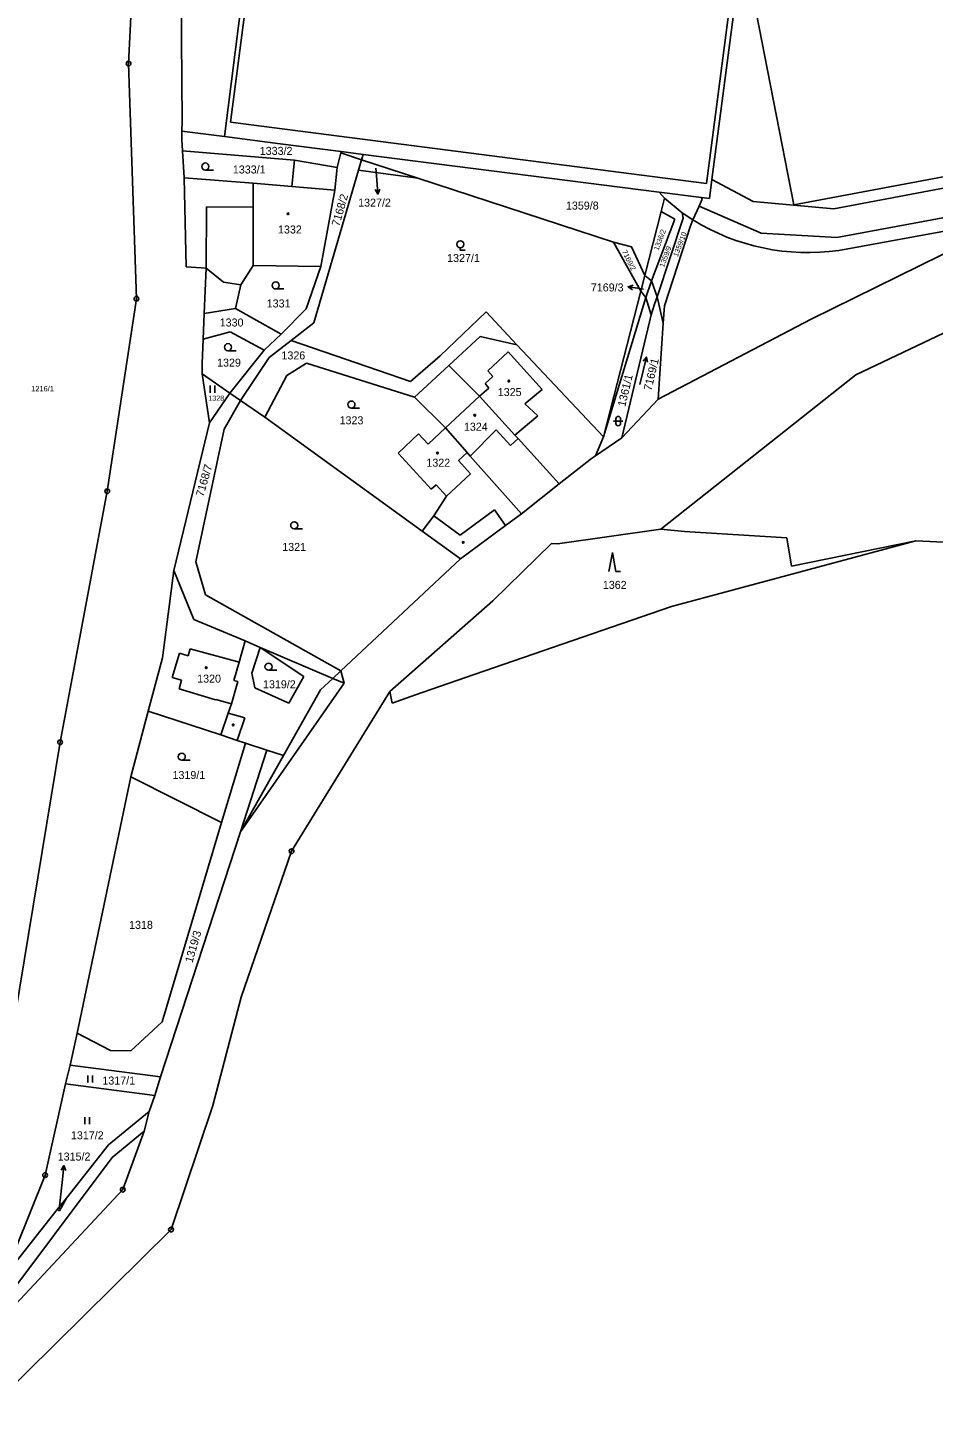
# Model space of a CAD drawing. Extents: x -593183 to -588034, y -1130415 to -1124994.
# Drawn here: x -590703 to -590510.6, y -1129694.1 to -1129397 of the extents above; entities that cross this region are included whole.
import ezdxf

# ---------------------------------------------------------------- set-up
doc = ezdxf.new("R2010")
doc.units = 0
for name, color, linetype in [('Vrstva 1', 7, 'Continuous'), ('Vrstva 13', 7, 'Continuous'), ('Vrstva 16', 7, 'Continuous'), ('Vrstva 18', 7, 'Continuous'), ('Vrstva 19', 7, 'Continuous'), ('Vrstva 24', 7, 'Continuous'), ('Vrstva 25', 7, 'Continuous'), ('Vrstva 4', 7, 'Continuous')]:
    doc.layers.add(name, color=color, linetype=linetype)

msp = doc.modelspace()

# ---------------------------------------------------------------- linework, layer by layer
at = {"layer": 'Vrstva 1'}
for p, q in [((-590652.25, -1129348.91), (-590661.21, -1129420.07)), ((-590651.35, -1129350.59), (-590659.9, -1129417.02)), ((-590558.75, -1129430.04), (-590550.17, -1129363.62)), ((-590681.59, -1129404.55), (-590680.19, -1129377.02)), ((-590557.61, -1129429.2), (-590551.06, -1129379.02)), ((-590670.2, -1129416.87), (-590670.5, -1129384.22)), ((-590679.92, -1129454.5), (-590681.59, -1129404.55)), ((-590670.25, -1129418.92), (-590670.3, -1129420.77)), ((-590670.2, -1129416.87), (-590670.25, -1129418.92)), ((-590661.21, -1129420.07), (-590670.25, -1129418.92)), ((-590659.9, -1129417.02), (-590558.75, -1129430.04)), ((-590670.3, -1129420.77), (-590670.15, -1129423.07)), ((-590661.21, -1129420.07), (-590649.4, -1129421.58)), ((-590649.4, -1129421.58), (-590636.39, -1129423.24)), ((-590670.15, -1129423.07), (-590646.32, -1129425.06)), ((-590669.77, -1129428.8), (-590670.15, -1129423.07)), ((-590646.32, -1129425.06), (-590646.91, -1129430.66)), ((-590637.29, -1129426.62), (-590646.32, -1129425.06)), ((-590636.47, -1129423.54), (-590637.29, -1129426.62)), ((-590636.47, -1129423.54), (-590636.39, -1129423.24)), ((-590632.06, -1129424.98), (-590636.47, -1129423.54)), ((-590636.39, -1129423.24), (-590631.72, -1129423.83)), ((-590632.72, -1129427.22), (-590632.06, -1129424.98)), ((-590632.06, -1129424.98), (-590620.12, -1129428.89)), ((-590631.72, -1129423.83), (-590568.82, -1129431.86)), ((-590632.72, -1129427.22), (-590642.23, -1129459.61)), ((-590637.29, -1129426.62), (-590637.73, -1129431.41)), ((-590632.72, -1129427.22), (-590620.12, -1129428.89)), ((-590655.13, -1129429.99), (-590669.77, -1129428.8)), ((-590669.77, -1129428.8), (-590669.38, -1129447.73)), ((-590646.91, -1129430.66), (-590655.13, -1129429.99)), ((-590578.55, -1129442.49), (-590620.12, -1129428.89)), ((-590558.13, -1129433.22), (-590557.61, -1129429.2)), ((-590530.66, -1129444.25), (-590444.73, -1129428.45)), ((-590637.73, -1129431.41), (-590640.71, -1129447.63)), ((-590568.82, -1129431.86), (-590559.81, -1129433.01)), ((-590568.82, -1129431.86), (-590567.69, -1129433.17)), ((-590567.69, -1129433.17), (-590568.42, -1129435.99)), ((-590563.93, -1129436.23), (-590567.69, -1129433.17)), ((-590559.81, -1129433.01), (-590558.13, -1129433.22)), ((-590571.89, -1129449.55), (-590568.42, -1129435.99)), ((-590565.52, -1129437.62), (-590568.42, -1129435.99)), ((-590563.7, -1129437.39), (-590563.93, -1129436.23)), ((-590561.65, -1129437.76), (-590563.93, -1129436.23)), ((-590570.44, -1129450.73), (-590565.52, -1129437.62)), ((-590569.27, -1129454.08), (-590563.7, -1129437.39)), ((-590567.72, -1129456), (-590562.2, -1129439)), ((-590562.2, -1129439), (-590561.65, -1129437.76)), ((-590574.68, -1129443.45), (-590578.55, -1129442.49)), ((-590572.76, -1129452.94), (-590578.55, -1129442.49)), ((-590571.89, -1129449.55), (-590574.68, -1129443.45)), ((-590504.32, -1129442.97), (-590536.56, -1129458.86)), ((-590669.38, -1129447.73), (-590665.08, -1129448.01)), ((-590665.08, -1129448.01), (-590665.51, -1129457.66)), ((-590655.09, -1129447.43), (-590657.7, -1129451.57)), ((-590640.71, -1129447.63), (-590655.09, -1129447.43)), ((-590643.82, -1129456.66), (-590640.71, -1129447.63)), ((-590657.7, -1129451.57), (-590658.85, -1129456.59)), ((-590571.89, -1129449.55), (-590572.76, -1129452.94)), ((-590571.89, -1129449.55), (-590570.44, -1129450.73)), ((-590569.27, -1129454.08), (-590570.44, -1129450.73)), ((-590686.13, -1129495.43), (-590679.92, -1129454.5)), ((-590580.69, -1129483.83), (-590572.76, -1129452.94)), ((-590572.76, -1129452.94), (-590571.65, -1129454.25)), ((-590571.65, -1129454.25), (-590570.5, -1129457.92)), ((-590569.27, -1129454.08), (-590569.81, -1129455.7)), ((-590567.96, -1129459.67), (-590569.27, -1129454.08)), ((-590665.75, -1129463.12), (-590665.51, -1129457.66)), ((-590665.51, -1129457.66), (-590658.85, -1129456.59)), ((-590658.85, -1129456.59), (-590649.19, -1129462.03)), ((-590649.19, -1129462.03), (-590643.82, -1129456.66)), ((-590605.57, -1129457.32), (-590615.37, -1129466.65)), ((-590599.08, -1129464.29), (-590605.57, -1129457.32)), ((-590569.81, -1129455.7), (-590570.5, -1129457.92)), ((-590567.96, -1129459.67), (-590567.72, -1129456)), ((-590642.23, -1129459.61), (-590647, -1129463.36)), ((-590570.5, -1129457.92), (-590576.74, -1129484.06)), ((-590536.56, -1129458.86), (-590569.06, -1129475.85)), ((-590569.06, -1129475.85), (-590567.96, -1129459.67)), ((-590665.98, -1129468.26), (-590665.75, -1129463.12)), ((-590665.75, -1129463.12), (-590659.99, -1129461.56)), ((-590659.99, -1129461.56), (-590652.8, -1129465.43)), ((-590652.8, -1129465.43), (-590649.19, -1129462.03)), ((-590647, -1129463.36), (-590651.72, -1129467.02)), ((-590621.67, -1129472.09), (-590647, -1129463.36)), ((-590613.52, -1129468.69), (-590606.87, -1129462.54)), ((-590606.87, -1129462.54), (-590599.08, -1129464.29)), ((-590506.95, -1129461.12), (-590527.01, -1129470.69)), ((-590660.06, -1129474.58), (-590652.8, -1129465.43)), ((-590615.37, -1129466.65), (-590621.67, -1129472.09)), ((-590580.69, -1129483.83), (-590599.08, -1129464.29)), ((-590665.97, -1129470.44), (-590665.98, -1129468.26)), ((-590651.72, -1129467.02), (-590657.78, -1129476.17)), ((-590647.93, -1129470.83), (-590643.75, -1129468.22)), ((-590643.75, -1129468.22), (-590620.84, -1129475.42)), ((-590620.84, -1129475.42), (-590613.52, -1129468.69)), ((-590606.98, -1129475.24), (-590613.52, -1129468.69)), ((-590660.06, -1129474.58), (-590665.97, -1129470.44)), ((-590665.97, -1129470.44), (-590664.4, -1129480.88)), ((-590652.65, -1129479.66), (-590647.93, -1129470.83)), ((-590527.01, -1129470.69), (-590568.51, -1129503.46)), ((-590664.4, -1129480.88), (-590660.06, -1129474.58)), ((-590660.06, -1129474.58), (-590657.78, -1129476.17)), ((-590620.84, -1129475.42), (-590614.26, -1129481.94)), ((-590599.5, -1129483.48), (-590606.98, -1129475.24)), ((-590661.28, -1129482.24), (-590657.78, -1129476.17)), ((-590657.78, -1129476.17), (-590652.65, -1129479.66)), ((-590569.06, -1129475.85), (-590576.74, -1129484.06)), ((-590671.95, -1129512.28), (-590664.4, -1129480.88)), ((-590652.65, -1129479.66), (-590619.21, -1129503.92)), ((-590667.32, -1129510.45), (-590661.28, -1129482.24)), ((-590624.3, -1129487.36), (-590619.98, -1129483.25)), ((-590619.98, -1129483.25), (-590617.92, -1129485.41)), ((-590617.92, -1129485.41), (-590614.26, -1129481.94)), ((-590614.26, -1129481.94), (-590609.62, -1129487.21)), ((-590598.82, -1129484.22), (-590599.5, -1129483.48)), ((-590590.05, -1129493.88), (-590598.82, -1129484.22)), ((-590582.37, -1129487.87), (-590580.69, -1129483.83)), ((-590576.74, -1129484.06), (-590582.37, -1129487.87)), ((-590617.27, -1129494.99), (-590624.3, -1129487.36)), ((-590609.62, -1129487.21), (-590608.97, -1129487.94)), ((-590608.97, -1129487.94), (-590598.12, -1129500.24)), ((-590590.05, -1129493.88), (-590583.18, -1129488.46)), ((-590583.18, -1129488.46), (-590582.37, -1129487.87)), ((-590696.13, -1129548.77), (-590686.13, -1129495.43)), ((-590616.25, -1129494.05), (-590617.27, -1129494.99)), ((-590614.05, -1129496.44), (-590616.25, -1129494.05)), ((-590598.12, -1129500.24), (-590590.05, -1129493.88)), ((-590616.75, -1129500.62), (-590614.05, -1129496.44)), ((-590619.21, -1129503.92), (-590616.75, -1129500.62)), ((-590598.12, -1129500.24), (-590601.46, -1129502.7)), ((-590619.21, -1129503.92), (-590611.07, -1129509.78)), ((-590601.46, -1129502.7), (-590611.07, -1129509.78)), ((-590568.51, -1129503.46), (-590590.46, -1129506.57)), ((-590568.51, -1129503.46), (-590563.45, -1129503.99)), ((-590563.45, -1129503.99), (-590541.69, -1129505.32)), ((-590591.68, -1129506.53), (-590604.17, -1129518.73)), ((-590590.46, -1129506.57), (-590591.68, -1129506.53)), ((-590541.69, -1129505.32), (-590540.74, -1129511.31)), ((-590540.74, -1129511.31), (-590514.31, -1129505.94)), ((-590665.26, -1129517.42), (-590667.32, -1129510.45)), ((-590611.07, -1129509.78), (-590636.49, -1129533.55)), ((-590671.95, -1129512.28), (-590674.4, -1129530.84)), ((-590671.95, -1129512.28), (-590667.72, -1129522.66)), ((-590636.49, -1129533.55), (-590665.26, -1129517.42)), ((-590626.07, -1129537.99), (-590604.17, -1129518.73)), ((-590667.72, -1129522.66), (-590656.83, -1129527.23)), ((-590668.93, -1129530.4), (-590668.49, -1129528.94)), ((-590668.49, -1129528.94), (-590658.12, -1129531.71)), ((-590658.12, -1129531.71), (-590656.83, -1129527.23)), ((-590656.83, -1129527.23), (-590653.6, -1129528.59)), ((-590653.6, -1129528.59), (-590655.36, -1129534.06)), ((-590644.33, -1129534.78), (-590653.6, -1129528.59)), ((-590638.2, -1129535.18), (-590653.6, -1129528.59)), ((-590674.4, -1129530.84), (-590677.42, -1129542.18)), ((-590672.3, -1129534.99), (-590670.77, -1129529.84)), ((-590670.77, -1129529.84), (-590668.93, -1129530.4)), ((-590670.32, -1129535.58), (-590672.3, -1129534.99)), ((-590655.36, -1129534.06), (-590654.79, -1129537.2)), ((-590647.56, -1129540.43), (-590644.33, -1129534.78)), ((-590635.75, -1129536.23), (-590636.49, -1129533.55)), ((-590670.87, -1129537.44), (-590670.32, -1129535.58)), ((-590663.09, -1129539.76), (-590670.87, -1129537.44)), ((-590657.82, -1129567.77), (-590635.75, -1129536.23)), ((-590654.79, -1129537.2), (-590647.56, -1129540.43)), ((-590635.75, -1129536.23), (-590638.2, -1129535.18)), ((-590663.06, -1129539.64), (-590663.09, -1129539.76)), ((-590659.73, -1129540.63), (-590663.06, -1129539.64)), ((-590660.4, -1129542.58), (-590659.73, -1129540.63)), ((-590677.42, -1129542.18), (-590681.12, -1129556.11)), ((-590662, -1129547.21), (-590660.4, -1129542.58)), ((-590709.58, -1129630.05), (-590696.13, -1129548.77)), ((-590658.48, -1129548.36), (-590662, -1129547.21)), ((-590661.81, -1129565.78), (-590656.77, -1129548.92)), ((-590656.77, -1129548.92), (-590658.48, -1129548.36)), ((-590652.18, -1129550.42), (-590656.77, -1129548.92)), ((-590657.82, -1129567.77), (-590652.18, -1129550.42)), ((-590681.12, -1129556.11), (-590692.5, -1129610.57)), ((-590681.12, -1129556.11), (-590661.81, -1129565.78)), ((-590674.47, -1129608.16), (-590661.81, -1129565.78)), ((-590674.77, -1129619.89), (-590657.82, -1129567.77)), ((-590681.14, -1129614.3), (-590674.47, -1129608.16)), ((-590692.5, -1129610.57), (-590694.03, -1129617.35)), ((-590692.5, -1129610.57), (-590685.44, -1129614.28)), ((-590685.44, -1129614.28), (-590681.14, -1129614.3)), ((-590694.03, -1129617.35), (-590694.99, -1129621.36)), ((-590694.03, -1129617.35), (-590674.77, -1129619.89)), ((-590674.77, -1129619.89), (-590676.02, -1129623.82)), ((-590694.99, -1129621.36), (-590699.32, -1129640.75)), ((-590676.02, -1129623.82), (-590694.99, -1129621.36)), ((-590676.02, -1129623.82), (-590677.2, -1129627.19)), ((-590685.83, -1129634.32), (-590677.2, -1129627.19)), ((-590677.2, -1129627.19), (-590678.26, -1129631.41)), ((-590678.26, -1129631.41), (-590685.08, -1129636.99)), ((-590678.26, -1129631.41), (-590682.83, -1129643.83)), ((-590685.83, -1129634.32), (-590694.79, -1129645.63)), ((-590685.08, -1129636.99), (-590715.46, -1129677.5)), ((-590699.32, -1129640.75), (-590705.56, -1129656.28)), ((-590682.83, -1129643.83), (-590716.23, -1129679.58)), ((-590696.73, -1129648.08), (-590694.79, -1129645.63)), ((-590694.79, -1129645.63), (-590696.27, -1129648.32)), ((-590696.73, -1129648.08), (-590717.48, -1129674.26)), ((-590696.27, -1129648.32), (-590696.73, -1129648.08))]:
    msp.add_line(p, q, dxfattribs=at)
msp.add_arc((-590537.21, -1129398.28), 46.43, 238.2367, 278.1071, dxfattribs=at)
at = {"layer": 'Vrstva 13'}
for p, q in [((-590566.2, -1129519.89), (-590514.31, -1129505.94)), ((-590514.31, -1129505.94), (-590429.15, -1129510.17)), ((-590608.16, -1129534.39), (-590566.2, -1129519.89)), ((-590617.37, -1129537.58), (-590608.16, -1129534.39)), ((-590620.63, -1129538.71), (-590617.37, -1129537.58)), ((-590646.94, -1129571.91), (-590626.07, -1129537.99)), ((-590626.07, -1129537.99), (-590625.57, -1129540.42)), ((-590625.57, -1129540.42), (-590620.63, -1129538.71)), ((-590657.66, -1129602.96), (-590646.94, -1129571.91)), ((-590663.66, -1129625.92), (-590657.66, -1129602.96)), ((-590672.57, -1129652.3), (-590663.66, -1129625.92)), ((-590714.83, -1129694.06), (-590672.57, -1129652.3))]:
    msp.add_line(p, q, dxfattribs=at)
at = {"layer": 'Vrstva 16'}
for p, q in [((-590629.07, -1129426.74), (-590628.86, -1129429.27)), ((-590572.13, -1129452.48), (-590572.46, -1129452.43)), ((-590696.37, -1129647.9), (-590695.66, -1129641.7))]:
    msp.add_line(p, q, dxfattribs=at)
at = {"layer": 'Vrstva 24'}
for centre, radius in [((-590681.59, -1129404.55), 0.5), ((-590681.59, -1129404.55), 0.0327), ((-590679.92, -1129454.5), 0.5), ((-590679.92, -1129454.5), 0.0327), ((-590686.13, -1129495.43), 0.5), ((-590686.13, -1129495.43), 0.0327), ((-590696.13, -1129548.77), 0.5), ((-590696.13, -1129548.77), 0.0327), ((-590646.94, -1129571.91), 0.5), ((-590646.94, -1129571.91), 0.0327), ((-590699.32, -1129640.75), 0.5), ((-590699.32, -1129640.75), 0.0327), ((-590682.83, -1129643.83), 0.5), ((-590682.83, -1129643.83), 0.0327), ((-590672.57, -1129652.3), 0.5), ((-590672.57, -1129652.3), 0.0327)]:
    msp.add_circle(centre, radius, dxfattribs=at)
at = {"layer": 'Vrstva 25'}
for p, q in [((-590663.51, -1129427.17), (-590665.26, -1129427.17)), ((-590628.86, -1129429.27), (-590628.61, -1129432.26)), ((-590611.09, -1129443.7), (-590611.09, -1129444.2)), ((-590611.09, -1129444.2), (-590610.07, -1129444.2)), ((-590648.58, -1129452.44), (-590650.33, -1129452.44)), ((-590572.46, -1129452.43), (-590575.42, -1129451.96)), ((-590658.71, -1129465.56), (-590660.46, -1129465.56)), ((-590572.93, -1129472.74), (-590571.53, -1129466.9)), ((-590664.26, -1129472.98), (-590664.26, -1129474.48)), ((-590663.23, -1129474.48), (-590663.23, -1129472.98)), ((-590632.48, -1129477.75), (-590634.23, -1129477.75)), ((-590578.54, -1129480.51), (-590576.54, -1129480.51)), ((-590578.04, -1129481.01), (-590578.04, -1129480.01)), ((-590577.04, -1129480.01), (-590577.04, -1129481.01)), ((-590644.63, -1129503.42), (-590646.38, -1129503.42)), ((-590578.77, -1129508.46), (-590579.51, -1129512.46)), ((-590578.77, -1129508.46), (-590578.04, -1129512.46)), ((-590578.04, -1129512.46), (-590577.04, -1129512.46)), ((-590650.1, -1129533.46), (-590651.85, -1129533.46)), ((-590668.53, -1129552.58), (-590670.28, -1129552.58)), ((-590690.27, -1129619.59), (-590690.27, -1129621.09)), ((-590689.24, -1129621.09), (-590689.24, -1129619.59)), ((-590690.89, -1129628.44), (-590690.89, -1129629.94)), ((-590689.86, -1129629.94), (-590689.86, -1129628.44)), ((-590695.66, -1129641.7), (-590695.32, -1129638.72))]:
    msp.add_line(p, q, dxfattribs=at)
for points in [[(-590628.2, -1129431.22), (-590628.61, -1129432.26), (-590629.19, -1129431.3)], [(-590574.51, -1129452.61), (-590575.42, -1129451.96), (-590574.36, -1129451.62)], [(-590572.25, -1129467.76), (-590571.53, -1129466.9), (-590571.28, -1129467.99)], [(-590695.93, -1129639.66), (-590695.32, -1129638.72), (-590694.94, -1129639.77)]]:
    msp.add_lwpolyline(points, dxfattribs=at)
for centre, radius in [((-590665.26, -1129426.42), 0.75), ((-590647.71, -1129436.46), 0.175), ((-590647.71, -1129436.46), 0.15), ((-590611.09, -1129442.95), 0.75), ((-590650.33, -1129451.69), 0.75), ((-590660.46, -1129464.81), 0.75), ((-590600.78, -1129472.02), 0.175), ((-590600.78, -1129472.02), 0.15), ((-590634.23, -1129477), 0.75), ((-590608.02, -1129479.26), 0.175), ((-590608.02, -1129479.26), 0.15), ((-590615.94, -1129487.31), 0.175), ((-590615.94, -1129487.31), 0.15), ((-590646.38, -1129502.67), 0.75), ((-590610.47, -1129506.29), 0.175), ((-590651.85, -1129532.71), 0.75), ((-590665.09, -1129532.92), 0.175), ((-590665.09, -1129532.92), 0.15), ((-590659.36, -1129545.07), 0.175), ((-590670.28, -1129551.83), 0.75)]:
    msp.add_circle(centre, radius, dxfattribs=at)
for centre, start, end in [((-590577.54, -1129480.01), 90, 180), ((-590577.54, -1129481.01), 180, 270), ((-590577.54, -1129480.01), 0, 90), ((-590577.54, -1129481.01), 270, 0)]:
    msp.add_arc(centre, 0.5, start, end, dxfattribs=at)
at = {"layer": 'Vrstva 4'}
for p, q in [((-590551.06, -1129379.02), (-590540.22, -1129434.55)), ((-590437.41, -1129415.2), (-590540.22, -1129434.55)), ((-590444.98, -1129419.12), (-590531.71, -1129435.39)), ((-590632.06, -1129424.98), (-590631.72, -1129423.83)), ((-590531.08, -1129441.52), (-590444.46, -1129425.31)), ((-590655.12, -1129435.05), (-590655.13, -1129429.99)), ((-590646.91, -1129430.66), (-590637.73, -1129431.41)), ((-590548.89, -1129433.84), (-590557.61, -1129429.2)), ((-590559.66, -1129433.34), (-590560.33, -1129434.82)), ((-590559.81, -1129433.01), (-590559.66, -1129433.34)), ((-590531.71, -1129435.39), (-590548.89, -1129433.84)), ((-590665.08, -1129448.01), (-590665.01, -1129435)), ((-590665.01, -1129435), (-590655.12, -1129435.05)), ((-590655.09, -1129447.43), (-590655.12, -1129435.05)), ((-590561.65, -1129437.76), (-590560.33, -1129434.82)), ((-590560.33, -1129434.82), (-590547.16, -1129440.58)), ((-590547.16, -1129440.58), (-590531.08, -1129441.52)), ((-590661.42, -1129451), (-590665.08, -1129448.01)), ((-590657.7, -1129451.57), (-590661.42, -1129451)), ((-590571.65, -1129454.25), (-590570.44, -1129450.73)), ((-590580.69, -1129483.83), (-590571.65, -1129454.25)), ((-590600.94, -1129465.8), (-590605.25, -1129469.86)), ((-590593.7, -1129473.79), (-590600.94, -1129465.8)), ((-590604.2, -1129471.02), (-590605.82, -1129472.55)), ((-590605.82, -1129472.55), (-590605.03, -1129473.49)), ((-590605.25, -1129469.86), (-590604.2, -1129471.02)), ((-590606.98, -1129475.24), (-590614.26, -1129481.94)), ((-590605.03, -1129473.49), (-590606.98, -1129475.24)), ((-590597.36, -1129476.88), (-590593.7, -1129473.79)), ((-590594.61, -1129479.39), (-590597.36, -1129476.88)), ((-590599.5, -1129483.48), (-590594.61, -1129479.39)), ((-590608.97, -1129487.94), (-590603.44, -1129482.4)), ((-590603.44, -1129482.4), (-590600.45, -1129485.7)), ((-590600.45, -1129485.7), (-590598.82, -1129484.22)), ((-590611.46, -1129488.91), (-590609.62, -1129487.21)), ((-590608.9, -1129491.69), (-590611.46, -1129488.91)), ((-590614.05, -1129496.44), (-590608.9, -1129491.69)), ((-590616.75, -1129500.62), (-590611.1, -1129504.77)), ((-590611.1, -1129504.77), (-590603.81, -1129499.39)), ((-590603.81, -1129499.39), (-590601.46, -1129502.7)), ((-590658.12, -1129531.71), (-590659.24, -1129535.61)), ((-590638.2, -1129535.18), (-590636.49, -1129533.55)), ((-590658.35, -1129535.86), (-590659.73, -1129540.63)), ((-590659.24, -1129535.61), (-590658.35, -1129535.86)), ((-590648.65, -1129551.57), (-590640.77, -1129537.65)), ((-590640.77, -1129537.65), (-590638.2, -1129535.18)), ((-590677.42, -1129542.18), (-590662, -1129547.21)), ((-590660.4, -1129542.58), (-590656.88, -1129543.59)), ((-590656.88, -1129543.59), (-590658.48, -1129548.36)), ((-590657.82, -1129567.77), (-590648.65, -1129551.57)), ((-590652.18, -1129550.42), (-590648.65, -1129551.57))]:
    msp.add_line(p, q, dxfattribs=at)

# ---------------------------------------------------------------- texts
at = {"layer": 'Vrstva 16'}
for s, height, p in [('1327/2', 1.7, (-590632.8, -1129434.94)), ('7169/3', 1.7, (-590583.35, -1129452.96)), ('1216/1', 1.14, (-590702.27, -1129474.19)), ('1315/2', 1.7, (-590696.65, -1129637.65))]:
    msp.add_text(s, height=height, dxfattribs=at).set_placement(p)
at = {"layer": 'Vrstva 18'}
for s, height, p in [('1333/2', 1.7, (-590653.71, -1129423.94)), ('1333/1', 1.7, (-590659.43, -1129427.9)), ('1327/2', 0.01, (-590629.07, -1129426.74)), ('1359/8', 1.7, (-590588.64, -1129435.57)), ('1327/1', 1.7, (-590613.89, -1129446.7)), ('1331', 1.7, (-590652.23, -1129456.36)), ('7169/3', 0.1, (-590572.13, -1129452.48)), ('1330', 1.7, (-590662.22, -1129460.41)), ('1326', 1.7, (-590649.1, -1129467.41)), ('1329', 1.7, (-590662.78, -1129468.94)), ('1328', 1.1, (-590664.65, -1129476.2)), ('1323', 1.7, (-590636.75, -1129481.2)), ('1321', 1.7, (-590648.93, -1129508.1)), ('1362', 1.7, (-590580.8, -1129516.17)), ('1319/2', 1.7, (-590653.02, -1129537.29)), ('1319/1', 1.7, (-590672.25, -1129556.57)), ('1318', 1.7, (-590681.48, -1129588.41)), ('1317/1', 1.7, (-590687.15, -1129621.49)), ('1317/2', 1.7, (-590693.84, -1129633.13))]:
    msp.add_text(s, height=height, dxfattribs=at).set_placement(p)
for s, height, rotation, p in [('7168/2', 1.7, 73.8987, (-590636.83, -1129439.23)), ('1336/2', 1.1, 69.4867, (-590568.99, -1129444.37)), ('1359/10', 1.1, 69.4867, (-590564.88, -1129445.7)), ('7169/2', 1.1, 296.565, (-590576.78, -1129444.49)), ('1359/9', 1.1, 69.4867, (-590567.81, -1129447.93)), ('7169/1', 1.7, 76.5644, (-590570.49, -1129474.15)), ('1361/1', 1.7, 76.5644, (-590576.04, -1129477.57)), ('7168/7', 1.7, 73.8987, (-590665.7, -1129496.69)), ('1319/3', 1.7, 73.9211, (-590668.02, -1129595.74)), ('1315/2', 0.1, 45, (-590696.33, -1129647.93))]:
    msp.add_text(s, height=height, rotation=rotation, dxfattribs=at).set_placement(p)
at = {"layer": 'Vrstva 19'}
for s, p in [('1332', (-590649.83, -1129440.65)), ('1325', (-590603.13, -1129475.19)), ('1324', (-590610.32, -1129482.56)), ('1322', (-590618.3, -1129490.21)), ('1320', (-590667.01, -1129536.09))]:
    msp.add_text(s, height=1.7, dxfattribs=at).set_placement(p)

doc.saveas('drawing.dxf')
